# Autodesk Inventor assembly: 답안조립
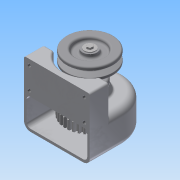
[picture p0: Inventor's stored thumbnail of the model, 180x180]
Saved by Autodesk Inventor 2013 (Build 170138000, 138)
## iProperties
Created: 2015-02
Part Number: 답안조립
Document SubType Name: Assembly
Designer: MYHOME
Author: MYHOME
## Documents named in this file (14)
- C:\Documents and Settings\MYHOME\바탕 화면\450214V1008\답안조립.iam
- C:\Documents and Settings\MYHOME\바탕 화면\450214V1008\1-본체.ipt
- C:\Documents and Settings\MYHOME\바탕 화면\450214V1008\키5x5.ipt
- C:\Documents and Settings\MYHOME\바탕 화면\450214V1008\축.ipt
- C:\Documents and Settings\MYHOME\바탕 화면\450214V1008\키4x4.ipt
- C:\Documents and Settings\MYHOME\바탕 화면\450214V1008\베어링 6001.ipt
- C:\Documents and Settings\MYHOME\바탕 화면\450214V1008\5-스퍼기어.ipt
- C:\Documents and Settings\MYHOME\바탕 화면\450214V1008\축커버.ipt
- C:\Documents and Settings\MYHOME\바탕 화면\450214V1008\오일실.ipt
- C:\Documents and Settings\MYHOME\바탕 화면\450214V1008\M3x0.5.ipt
- C:\Documents and Settings\MYHOME\바탕 화면\450214V1008\4-V벨트풀리.ipt
- C:\Documents and Settings\MYHOME\바탕 화면\450214V1008\M5x0.8.ipt
- M5x0.8.ipt
- C:\Documents and Settings\MYHOME\바탕 화면\450214V1008\와샤.ipt
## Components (7 placed, 4 different names)
1. 1-본체:1
2. 4-V벨트풀리:1 — 플러쉬:1, 각도:4
3. M5x0.8:1
4. M3x0.5:1
5. M3x0.5:2
6. M3x0.5:3
7. M3x0.5:4
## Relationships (2: Flush 1, Angle 1)
- 플러쉬:1 [Flush]: 4-V벨트풀리:1
- 각도:4 [Angle]: 4-V벨트풀리:1
